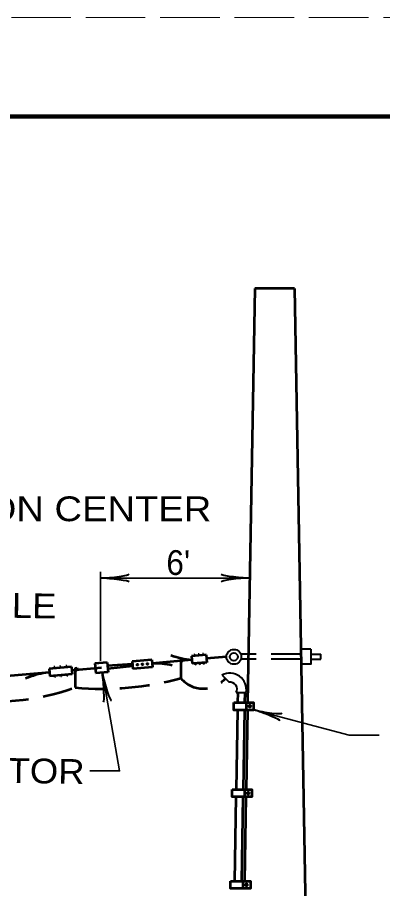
# Model space of a CAD drawing. Extents: x 12366 to 13046, y 9129 to 9570.
# Drawn here: x 12629.1 to 12665.9, y 9481.6 to 9569.5 of the extents above; entities that cross this region are included whole.
import ezdxf
from ezdxf.enums import TextEntityAlignment as Align

# ---------------------------------------------------------------- set-up
doc = ezdxf.new("R2010")
doc.units = 0
doc.linetypes.add('LONG_DASHED', pattern=[7.5, 6, -1.5])
doc.linetypes.add('MEDIUM_DASHED', pattern=[4.5, 3, -1.5])
doc.layers.add('1', color=7, linetype='Continuous', lineweight=53)
doc.layers.add('61', color=7, linetype='Continuous', lineweight=35)

msp = doc.modelspace()

# ---------------------------------------------------------------- linework, layer by layer
at = {"layer": '1'}
for p, q in [((12653.031, 9542.164), (12652.302, 9500.379)), ((12657.031, 9542.164), (12653.031, 9542.164)), ((12657.031, 9542.164), (12659.562, 9397.186)), ((12648.144, 9505.178), (12646.649, 9505.047)), ((12647.019, 9505.18), (12646.919, 9505.171)), ((12646.919, 9505.171), (12646.928, 9505.071)), ((12646.927, 9505.172), (12646.936, 9505.072)), ((12646.93, 9505.172), (12646.939, 9505.072)), ((12646.935, 9505.172), (12646.944, 9505.073)), ((12646.943, 9505.173), (12646.952, 9505.073)), ((12646.949, 9505.173), (12646.957, 9505.074)), ((12646.95, 9505.174), (12646.959, 9505.074)), ((12646.956, 9505.174), (12646.965, 9505.075)), ((12646.962, 9505.175), (12646.97, 9505.075)), ((12646.966, 9505.175), (12646.974, 9505.075)), ((12646.975, 9505.176), (12646.984, 9505.076)), ((12646.982, 9505.176), (12646.991, 9505.077)), ((12646.992, 9505.177), (12647, 9505.078)), ((12646.993, 9505.177), (12647.002, 9505.078)), ((12646.995, 9505.178), (12647.004, 9505.078)), ((12646.997, 9505.178), (12647.006, 9505.078)), ((12647.001, 9505.178), (12647.01, 9505.078)), ((12647.008, 9505.179), (12647.017, 9505.079)), ((12647.012, 9505.179), (12647.021, 9505.079)), ((12647.019, 9505.18), (12647.028, 9505.08)), ((12647.438, 9505.216), (12647.338, 9505.208)), ((12647.338, 9505.208), (12647.346, 9505.108)), ((12647.341, 9505.208), (12647.349, 9505.108)), ((12647.35, 9505.209), (12647.358, 9505.109)), ((12647.357, 9505.209), (12647.366, 9505.11)), ((12647.365, 9505.21), (12647.373, 9505.11)), ((12647.374, 9505.211), (12647.383, 9505.111)), ((12647.376, 9505.211), (12647.385, 9505.111)), ((12647.384, 9505.212), (12647.392, 9505.112)), ((12647.388, 9505.212), (12647.396, 9505.112)), ((12647.391, 9505.212), (12647.4, 9505.113)), ((12647.397, 9505.213), (12647.406, 9505.113)), ((12647.401, 9505.213), (12647.41, 9505.113)), ((12647.407, 9505.214), (12647.415, 9505.114)), ((12647.414, 9505.214), (12647.423, 9505.115)), ((12647.418, 9505.215), (12647.427, 9505.115)), ((12647.42, 9505.215), (12647.429, 9505.115)), ((12647.422, 9505.215), (12647.43, 9505.115)), ((12647.43, 9505.216), (12647.439, 9505.116)), ((12647.438, 9505.216), (12647.446, 9505.117)), ((12647.856, 9505.253), (12647.756, 9505.244)), ((12647.756, 9505.244), (12647.765, 9505.145)), ((12647.761, 9505.245), (12647.77, 9505.145)), ((12647.77, 9505.245), (12647.779, 9505.146)), ((12647.777, 9505.246), (12647.786, 9505.146)), ((12647.787, 9505.247), (12647.796, 9505.147)), ((12647.787, 9505.247), (12647.796, 9505.147)), ((12647.792, 9505.247), (12647.801, 9505.148)), ((12647.798, 9505.248), (12647.807, 9505.148)), ((12647.8, 9505.248), (12647.809, 9505.148)), ((12647.806, 9505.248), (12647.815, 9505.149)), ((12647.813, 9505.249), (12647.822, 9505.15)), ((12647.819, 9505.25), (12647.828, 9505.15)), ((12647.829, 9505.251), (12647.838, 9505.151)), ((12647.833, 9505.251), (12647.842, 9505.151)), ((12647.839, 9505.251), (12647.847, 9505.152)), ((12647.842, 9505.252), (12647.851, 9505.152)), ((12647.848, 9505.252), (12647.857, 9505.153)), ((12647.856, 9505.253), (12647.865, 9505.153)), ((12648.144, 9505.178), (12648.209, 9504.431)), ((12638.16, 9504.428), (12636.915, 9504.319)), ((12636.915, 9504.319), (12637.002, 9503.323)), ((12638.16, 9504.428), (12638.248, 9503.432)), ((12642.664, 9504.699), (12640.672, 9504.524)), ((12640.672, 9504.524), (12640.737, 9503.777)), ((12642.664, 9504.699), (12642.73, 9503.951)), ((12646.682, 9504.673), (12642.697, 9504.325)), ((12645.562, 9504.779), (12645.761, 9504.796)), ((12645.562, 9504.779), (12645.579, 9504.579)), ((12645.566, 9504.729), (12645.716, 9504.742)), ((12645.566, 9504.729), (12645.579, 9504.579)), ((12645.575, 9504.78), (12645.593, 9504.581)), ((12645.579, 9504.579), (12645.779, 9504.597)), ((12645.579, 9504.579), (12645.729, 9504.592)), ((12645.579, 9504.579), (12645.579, 9502.829)), ((12645.58, 9504.73), (12645.593, 9504.581)), ((12645.591, 9504.781), (12645.608, 9504.582)), ((12645.595, 9504.731), (12645.608, 9504.582)), ((12645.606, 9504.783), (12645.623, 9504.583)), ((12645.61, 9504.733), (12645.623, 9504.583)), ((12645.621, 9504.784), (12645.638, 9504.585)), ((12645.625, 9504.734), (12645.638, 9504.585)), ((12645.629, 9504.785), (12645.646, 9504.585)), ((12645.639, 9504.785), (12645.657, 9504.586)), ((12645.644, 9504.736), (12645.657, 9504.586)), ((12645.651, 9504.786), (12645.668, 9504.587)), ((12645.655, 9504.737), (12645.668, 9504.587)), ((12645.661, 9504.787), (12645.679, 9504.588)), ((12645.67, 9504.788), (12645.687, 9504.589)), ((12645.674, 9504.738), (12645.687, 9504.589)), ((12645.685, 9504.789), (12645.702, 9504.59)), ((12645.689, 9504.74), (12645.702, 9504.59)), ((12645.7, 9504.791), (12645.717, 9504.592)), ((12645.704, 9504.741), (12645.717, 9504.592)), ((12645.711, 9504.792), (12645.729, 9504.592)), ((12645.716, 9504.742), (12645.729, 9504.592)), ((12645.722, 9504.793), (12645.74, 9504.593)), ((12645.732, 9504.793), (12645.749, 9504.594)), ((12645.742, 9504.794), (12645.759, 9504.595)), ((12645.752, 9504.795), (12645.769, 9504.596)), ((12645.761, 9504.796), (12645.779, 9504.597)), ((12646.649, 9505.047), (12646.715, 9504.3)), ((12648.209, 9504.431), (12646.715, 9504.3)), ((12646.994, 9504.324), (12647.002, 9504.224)), ((12647.003, 9504.325), (12647.012, 9504.224)), ((12647.007, 9504.325), (12647.015, 9504.225)), ((12647.012, 9504.326), (12647.021, 9504.225)), ((12647.018, 9504.326), (12647.027, 9504.226)), ((12647.025, 9504.327), (12647.034, 9504.226)), ((12647.034, 9504.328), (12647.043, 9504.227)), ((12647.042, 9504.328), (12647.051, 9504.228)), ((12647.047, 9504.329), (12647.056, 9504.228)), ((12647.055, 9504.33), (12647.064, 9504.229)), ((12647.062, 9504.33), (12647.071, 9504.23)), ((12647.072, 9504.331), (12647.081, 9504.23)), ((12647.074, 9504.331), (12647.082, 9504.231)), ((12647.075, 9504.331), (12647.084, 9504.231)), ((12647.083, 9504.332), (12647.092, 9504.231)), ((12647.093, 9504.333), (12647.102, 9504.232)), ((12647.412, 9504.361), (12647.421, 9504.26)), ((12647.416, 9504.361), (12647.425, 9504.261)), ((12647.424, 9504.362), (12647.432, 9504.261)), ((12647.429, 9504.362), (12647.438, 9504.262)), ((12647.439, 9504.363), (12647.447, 9504.262)), ((12647.441, 9504.363), (12647.449, 9504.263)), ((12647.453, 9504.364), (12647.462, 9504.264)), ((12647.462, 9504.365), (12647.471, 9504.265)), ((12647.476, 9504.366), (12647.485, 9504.266)), ((12647.483, 9504.367), (12647.492, 9504.266)), ((12647.489, 9504.368), (12647.498, 9504.267)), ((12647.496, 9504.368), (12647.505, 9504.268)), ((12647.506, 9504.369), (12647.515, 9504.268)), ((12647.512, 9504.37), (12647.52, 9504.269)), ((12647.83, 9504.397), (12647.839, 9504.297)), ((12647.839, 9504.398), (12647.848, 9504.298)), ((12647.939, 9504.306), (12647.839, 9504.297)), ((12647.844, 9504.399), (12647.853, 9504.298)), ((12647.848, 9504.399), (12647.857, 9504.298)), ((12647.851, 9504.399), (12647.86, 9504.299)), ((12647.852, 9504.399), (12647.86, 9504.299)), ((12647.859, 9504.4), (12647.868, 9504.299)), ((12647.865, 9504.4), (12647.874, 9504.3)), ((12647.87, 9504.401), (12647.879, 9504.3)), ((12647.878, 9504.402), (12647.886, 9504.301)), ((12647.882, 9504.402), (12647.891, 9504.301)), ((12647.887, 9504.403), (12647.896, 9504.302)), ((12647.893, 9504.403), (12647.902, 9504.302)), ((12647.901, 9504.404), (12647.909, 9504.303)), ((12647.906, 9504.404), (12647.915, 9504.303)), ((12647.914, 9504.405), (12647.923, 9504.304)), ((12647.914, 9504.405), (12647.923, 9504.304)), ((12647.918, 9504.405), (12647.927, 9504.305)), ((12647.924, 9504.406), (12647.932, 9504.305)), ((12647.93, 9504.406), (12647.939, 9504.306)), ((12650.169, 9504.978), (12648.176, 9504.804)), ((12632.351, 9503.418), (12561.823, 9497.248)), ((12634.56, 9503.988), (12632.319, 9503.792)), ((12632.319, 9503.792), (12632.384, 9503.045)), ((12632.87, 9503.943), (12632.77, 9503.934)), ((12632.779, 9503.832), (12632.77, 9503.934)), ((12632.78, 9503.832), (12632.771, 9503.934)), ((12632.782, 9503.832), (12632.773, 9503.935)), ((12632.791, 9503.833), (12632.782, 9503.935)), ((12632.793, 9503.833), (12632.784, 9503.936)), ((12632.793, 9503.833), (12632.784, 9503.936)), ((12632.802, 9503.834), (12632.793, 9503.936)), ((12632.804, 9503.834), (12632.795, 9503.936)), ((12632.804, 9503.834), (12632.795, 9503.936)), ((12632.809, 9503.835), (12632.8, 9503.937)), ((12632.81, 9503.835), (12632.801, 9503.937)), ((12632.817, 9503.835), (12632.808, 9503.938)), ((12632.826, 9503.836), (12632.817, 9503.939)), ((12632.828, 9503.836), (12632.819, 9503.939)), ((12632.834, 9503.837), (12632.825, 9503.939)), ((12632.841, 9503.838), (12632.832, 9503.94)), ((12632.848, 9503.838), (12632.839, 9503.94)), ((12632.848, 9503.838), (12632.839, 9503.94)), ((12632.854, 9503.839), (12632.845, 9503.941)), ((12632.86, 9503.839), (12632.851, 9503.941)), ((12632.863, 9503.84), (12632.854, 9503.942)), ((12632.863, 9503.84), (12632.855, 9503.942)), ((12632.871, 9503.84), (12632.862, 9503.942)), ((12632.875, 9503.841), (12632.866, 9503.943)), ((12632.879, 9503.841), (12632.87, 9503.943)), ((12633.48, 9503.996), (12633.381, 9503.987)), ((12633.39, 9503.886), (12633.381, 9503.987)), ((12633.396, 9503.886), (12633.387, 9503.988)), ((12633.4, 9503.887), (12633.391, 9503.988)), ((12633.404, 9503.887), (12633.395, 9503.989)), ((12633.411, 9503.887), (12633.402, 9503.989)), ((12633.414, 9503.888), (12633.405, 9503.99)), ((12633.416, 9503.888), (12633.407, 9503.99)), ((12633.424, 9503.889), (12633.415, 9503.99)), ((12633.431, 9503.889), (12633.422, 9503.991)), ((12633.431, 9503.889), (12633.423, 9503.991)), ((12633.431, 9503.889), (12633.423, 9503.991)), ((12633.435, 9503.89), (12633.426, 9503.991)), ((12633.44, 9503.89), (12633.431, 9503.992)), ((12633.441, 9503.89), (12633.432, 9503.992)), ((12633.444, 9503.89), (12633.435, 9503.992)), ((12633.452, 9503.891), (12633.443, 9503.993)), ((12633.452, 9503.891), (12633.443, 9503.993)), ((12633.456, 9503.891), (12633.447, 9503.993)), ((12633.457, 9503.891), (12633.448, 9503.993)), ((12633.459, 9503.892), (12633.45, 9503.994)), ((12633.459, 9503.892), (12633.45, 9503.994)), ((12633.463, 9503.892), (12633.454, 9503.994)), ((12633.465, 9503.892), (12633.456, 9503.994)), ((12633.47, 9503.893), (12633.461, 9503.994)), ((12633.474, 9503.893), (12633.465, 9503.995)), ((12633.478, 9503.893), (12633.469, 9503.995)), ((12633.48, 9503.894), (12633.471, 9503.995)), ((12633.483, 9503.894), (12633.474, 9503.996)), ((12633.489, 9503.894), (12633.48, 9503.996)), ((12634.091, 9504.041), (12633.992, 9504.032)), ((12634, 9503.939), (12633.992, 9504.032)), ((12634.008, 9503.94), (12634, 9504.033)), ((12634.01, 9503.94), (12634.002, 9504.033)), ((12634.012, 9503.94), (12634.004, 9504.033)), ((12634.019, 9503.941), (12634.011, 9504.034)), ((12634.021, 9503.941), (12634.013, 9504.034)), ((12634.023, 9503.941), (12634.015, 9504.034)), ((12634.029, 9503.942), (12634.021, 9504.035)), ((12634.036, 9503.942), (12634.028, 9504.035)), ((12634.038, 9503.942), (12634.03, 9504.036)), ((12634.045, 9503.943), (12634.037, 9504.036)), ((12634.051, 9503.943), (12634.043, 9504.037)), ((12634.057, 9503.944), (12634.048, 9504.037)), ((12634.06, 9503.944), (12634.052, 9504.038)), ((12634.066, 9503.945), (12634.058, 9504.038)), ((12634.074, 9503.945), (12634.066, 9504.039)), ((12634.078, 9503.946), (12634.07, 9504.039)), ((12634.083, 9503.946), (12634.075, 9504.04)), ((12634.091, 9503.947), (12634.082, 9504.04)), ((12634.096, 9503.947), (12634.088, 9504.041)), ((12634.099, 9503.948), (12634.091, 9504.041)), ((12634.56, 9503.988), (12634.626, 9503.241)), ((12637.581, 9503.876), (12634.593, 9503.614)), ((12634.92, 9503.846), (12635.119, 9503.863)), ((12634.92, 9503.846), (12634.938, 9503.646)), ((12634.924, 9503.796), (12635.074, 9503.809)), ((12634.924, 9503.796), (12634.938, 9503.646)), ((12634.934, 9503.847), (12634.951, 9503.648)), ((12634.938, 9503.797), (12634.951, 9503.648)), ((12634.938, 9503.646), (12635.137, 9503.664)), ((12634.938, 9503.646), (12635.087, 9503.659)), ((12634.938, 9503.646), (12634.938, 9501.896)), ((12634.949, 9503.848), (12634.966, 9503.649)), ((12634.953, 9503.798), (12634.966, 9503.649)), ((12634.964, 9503.849), (12634.981, 9503.65)), ((12634.968, 9503.799), (12634.981, 9503.65)), ((12634.979, 9503.851), (12634.996, 9503.651)), ((12634.983, 9503.801), (12634.996, 9503.651)), ((12634.987, 9503.851), (12635.004, 9503.652)), ((12634.997, 9503.852), (12635.015, 9503.653)), ((12635.002, 9503.802), (12635.015, 9503.653)), ((12635.009, 9503.853), (12635.026, 9503.654)), ((12635.013, 9503.803), (12635.026, 9503.654)), ((12635.02, 9503.854), (12635.037, 9503.655)), ((12635.028, 9503.855), (12635.045, 9503.656)), ((12635.032, 9503.805), (12635.045, 9503.656)), ((12635.043, 9503.856), (12635.06, 9503.657)), ((12635.047, 9503.806), (12635.06, 9503.657)), ((12635.058, 9503.858), (12635.075, 9503.658)), ((12635.062, 9503.808), (12635.075, 9503.658)), ((12635.07, 9503.859), (12635.087, 9503.659)), ((12635.074, 9503.809), (12635.087, 9503.659)), ((12635.08, 9503.86), (12635.098, 9503.66)), ((12635.09, 9503.86), (12635.107, 9503.661)), ((12635.1, 9503.861), (12635.118, 9503.662)), ((12635.11, 9503.862), (12635.127, 9503.663)), ((12635.119, 9503.863), (12635.137, 9503.664)), ((12638.248, 9503.432), (12637.002, 9503.323)), ((12640.696, 9504.247), (12638.192, 9504.072)), ((12640.713, 9504.051), (12638.216, 9503.789)), ((12642.73, 9503.951), (12640.737, 9503.777)), ((12647.102, 9504.232), (12647.002, 9504.224)), ((12647.52, 9504.269), (12647.421, 9504.26)), ((12633.505, 9503.143), (12632.384, 9503.045)), ((12632.854, 9502.985), (12632.845, 9503.085)), ((12632.86, 9502.986), (12632.851, 9503.086)), ((12632.953, 9502.994), (12632.854, 9502.985)), ((12632.869, 9502.987), (12632.86, 9503.086)), ((12632.875, 9502.987), (12632.866, 9503.087)), ((12632.878, 9502.988), (12632.87, 9503.087)), ((12632.88, 9502.988), (12632.872, 9503.087)), ((12632.882, 9502.988), (12632.874, 9503.087)), ((12632.888, 9502.988), (12632.879, 9503.088)), ((12632.888, 9502.988), (12632.879, 9503.088)), ((12632.897, 9502.989), (12632.888, 9503.089)), ((12632.903, 9502.99), (12632.894, 9503.089)), ((12632.905, 9502.99), (12632.896, 9503.09)), ((12632.908, 9502.99), (12632.9, 9503.09)), ((12632.908, 9502.99), (12632.9, 9503.09)), ((12632.918, 9502.991), (12632.909, 9503.091)), ((12632.925, 9502.992), (12632.916, 9503.091)), ((12632.931, 9502.992), (12632.922, 9503.092)), ((12632.933, 9502.992), (12632.924, 9503.092)), ((12632.934, 9502.993), (12632.926, 9503.092)), ((12632.936, 9502.993), (12632.928, 9503.092)), ((12632.94, 9502.993), (12632.931, 9503.093)), ((12632.944, 9502.993), (12632.935, 9503.093)), ((12632.945, 9502.994), (12632.937, 9503.093)), ((12632.953, 9502.994), (12632.944, 9503.094)), ((12633.464, 9503.039), (12633.455, 9503.138)), ((12633.467, 9503.039), (12633.459, 9503.139)), ((12633.563, 9503.048), (12633.464, 9503.039)), ((12633.475, 9503.04), (12633.466, 9503.139)), ((12633.475, 9503.04), (12633.466, 9503.139)), ((12633.477, 9503.04), (12633.468, 9503.14)), ((12633.486, 9503.041), (12633.477, 9503.14)), ((12633.49, 9503.041), (12633.481, 9503.141)), ((12633.497, 9503.042), (12633.489, 9503.141)), ((12633.499, 9503.042), (12633.491, 9503.141)), ((12633.507, 9503.043), (12633.498, 9503.142)), ((12633.51, 9503.043), (12633.502, 9503.142)), ((12634.626, 9503.241), (12633.505, 9503.143)), ((12633.513, 9503.043), (12633.505, 9503.143)), ((12633.518, 9503.044), (12633.509, 9503.143)), ((12633.518, 9503.044), (12633.509, 9503.143)), ((12633.525, 9503.044), (12633.517, 9503.144)), ((12633.533, 9503.045), (12633.524, 9503.144)), ((12633.536, 9503.045), (12633.528, 9503.145)), ((12633.542, 9503.046), (12633.534, 9503.145)), ((12633.547, 9503.046), (12633.539, 9503.146)), ((12633.547, 9503.046), (12633.539, 9503.146)), ((12633.557, 9503.047), (12633.548, 9503.146)), ((12633.563, 9503.048), (12633.555, 9503.147)), ((12634.074, 9503.092), (12634.065, 9503.192)), ((12634.078, 9503.093), (12634.07, 9503.192)), ((12634.082, 9503.093), (12634.073, 9503.193)), ((12634.173, 9503.101), (12634.074, 9503.092)), ((12634.091, 9503.094), (12634.083, 9503.193)), ((12634.101, 9503.095), (12634.092, 9503.194)), ((12634.107, 9503.095), (12634.098, 9503.195)), ((12634.114, 9503.096), (12634.105, 9503.195)), ((12634.121, 9503.096), (12634.112, 9503.196)), ((12634.125, 9503.097), (12634.117, 9503.196)), ((12634.128, 9503.097), (12634.119, 9503.197)), ((12634.136, 9503.098), (12634.128, 9503.197)), ((12634.136, 9503.098), (12634.128, 9503.197)), ((12634.144, 9503.098), (12634.135, 9503.198)), ((12634.145, 9503.099), (12634.137, 9503.198)), ((12634.155, 9503.099), (12634.146, 9503.199)), ((12634.155, 9503.099), (12634.146, 9503.199)), ((12634.162, 9503.1), (12634.154, 9503.199)), ((12634.17, 9503.101), (12634.162, 9503.2)), ((12634.173, 9503.101), (12634.165, 9503.2)), ((12651.318, 9501.38), (12651.3, 9500.379)), ((12652.018, 9501.38), (12652, 9500.364)), ((12652.152, 9500.371), (12652.152, 9499.621)), ((12651.287, 9499.621), (12651.147, 9491.608)), ((12651.987, 9499.613), (12651.847, 9491.608)), ((12652.289, 9499.605), (12652.149, 9491.608)), ((12651.994, 9491.6), (12651.994, 9490.85)), ((12651.134, 9490.857), (12650.986, 9482.352)), ((12651.834, 9490.842), (12651.686, 9482.352)), ((12652.136, 9490.849), (12651.987, 9482.348)), ((12651.832, 9482.348), (12651.832, 9481.598))]:
    msp.add_line(p, q, dxfattribs=at)
at = {"layer": '1', "lineweight": 35}
for p, q in [((12637.479, 9504.581), (12637.479, 9513.581)), ((12637.479, 9512.941), (12652.521, 9512.941))]:
    msp.add_line(p, q, dxfattribs=at)
at = {"layer": '1', "linetype": 'MEDIUM_DASHED', "lineweight": 40}
for p, q in [((12657.678, 9505.254), (12651.636, 9505.254)), ((12657.678, 9504.754), (12651.636, 9504.754))]:
    msp.add_line(p, q, dxfattribs=at)
at = {"layer": '1', "lineweight": 40}
for p, q in [((12658.694, 9505.754), (12657.688, 9505.754)), ((12658.694, 9505.254), (12659.678, 9505.254)), ((12659.678, 9504.754), (12659.678, 9505.254)), ((12658.694, 9504.754), (12659.678, 9504.754)), ((12649.724, 9503.132), (12650.431, 9502.425)), ((12651.152, 9501.38), (12652.152, 9501.38))]:
    msp.add_line(p, q, dxfattribs=at)
at = {"layer": '1', "lineweight": 25}
for p, q in [((12642.697, 9504.325), (12642.898, 9504.342)), ((12648.176, 9504.804), (12648.421, 9504.826)), ((12632.351, 9503.418), (12631.971, 9503.385)), ((12634.593, 9503.614), (12634.984, 9503.649))]:
    msp.add_line(p, q, dxfattribs=at)
at = {"layer": '1', "lineweight": 40}
msp.add_lwpolyline([(12658.694, 9505.754), (12658.694, 9504.254), (12657.691, 9504.254)], dxfattribs=at)
at = {"layer": '1', "lineweight": 35}
for points in [[(12637.672, 9503.327), (12639.409, 9493.479), (12636.409, 9493.479)], [(12652.894, 9499.655), (12662.553, 9497.067), (12665.553, 9497.067)]]:
    msp.add_lwpolyline(points, dxfattribs=at)
at = {"layer": '1'}
for points in [[(12650.902, 9500.371), (12652.902, 9500.371), (12652.902, 9499.621), (12650.902, 9499.621)], [(12650.744, 9491.6), (12652.744, 9491.6), (12652.744, 9490.85), (12650.744, 9490.85)], [(12650.582, 9482.348), (12652.582, 9482.348), (12652.582, 9481.598), (12650.582, 9481.598)]]:
    msp.add_lwpolyline(points, close=True, dxfattribs=at)
at = {"layer": '1', "lineweight": 40}
for centre, radius in [((12650.92, 9504.989), 0.75), ((12650.923, 9504.987), 0.394)]:
    msp.add_circle(centre, radius, dxfattribs=at)
at = {"layer": '1'}
for centre, radius in [((12641.703, 9504.24), 0.05), ((12642.201, 9504.281), 0.05), ((12641.205, 9504.195), 0.05), ((12652.516, 9500), 0.1), ((12652.358, 9491.228), 0.1), ((12652.196, 9481.977), 0.1)]:
    msp.add_circle(centre, radius, dxfattribs=at)
for centre, start, end in [((12642.878, 9495.635), 77.79454, 91.19453), ((12647.561, 9513.321), 249.94661, 264.19453), ((12633.301, 9494.796), 98.80547, 112.81313)]:
    msp.add_arc(centre, 8.692, start, end, dxfattribs=at)
at = {"layer": '1', "linetype": 'MEDIUM_DASHED'}
for centre, radius, start, end in [((12637.716, 9531.352), 29.587, 264.61066, 285.41207), ((12647.834, 9504.723), 2.944, 220.02355, 318.67214), ((12626.841, 9524.298), 23.82, 260.14661, 289.87015)]:
    msp.add_arc(centre, radius, start, end, dxfattribs=at)
at = {"layer": '1', "lineweight": 40}
for centre, radius, start, end in [((12650.523, 9501.682), 1.656, 349.50124, 118.8707), ((12650.533, 9501.725), 0.708, 330.86779, 98.35179)]:
    msp.add_arc(centre, radius, start, end, dxfattribs=at)
for centre, major_axis, ratio, start_param, end_param in [((12638.57, 9513.218), (-1.786, -0.156), 0.122415, 0.896353, 3.141593), ((12651.401, 9513.153), (1.756, -0.176), 0.07063, 3.140715, 5.41811), ((12638.6, 9512.73), (1.756, -0.176), 0.07063, 6.282307, 8.559703), ((12651.43, 9512.665), (1.786, 0.156), 0.122415, 0.896353, 3.141593), ((12637.658, 9502.187), (-0.132, 1.76), 0.07063, 3.140715, 5.41811), ((12638.134, 9502.3), (-0.464, 1.731), 0.122415, 0.896353, 3.141593), ((12653.922, 9499.161), (1.651, -0.624), 0.07063, 6.282307, 8.559703), ((12654.02, 9499.64), (-1.765, 0.311), 0.122415, 0.896353, 3.141593)]:
    msp.add_ellipse(centre, major_axis=major_axis, ratio=ratio, start_param=start_param, end_param=end_param, dxfattribs=at)
at = {"layer": '61', "linetype": 'LONG_DASHED', "lineweight": 13}
msp.add_line((12365.992, 9569.533), (13046.012, 9569.533), dxfattribs=at)
at = {"layer": '61', "lineweight": 158}
msp.add_lwpolyline([(13035.032, 9559.533), (12395.992, 9559.533), (12395.992, 9139.513)], dxfattribs=at)

# ---------------------------------------------------------------- texts
at = {"layer": '1', "width": 1.15}
msp.add_text('CABLE RINGS 15" ON CENTER', height=2.5, dxfattribs=at).set_placement((12592.377, 9518.681))
at = {"layer": '1', "width": 0.95}
msp.add_text("6'", height=2.5, rotation=359, dxfattribs=at).set_placement((12645.283, 9513.25), align=Align.CENTER)
at = {"layer": '1', "width": 1.1}
msp.add_text('MESSENGER CABLE', height=2.5, rotation=359, dxfattribs=at).set_placement((12596.444, 9509.494))
msp.add_text('STRAIN INSULATOR', height=2.5, rotation=359, dxfattribs=at).set_placement((12635.852, 9492.139), align=Align.RIGHT)

doc.saveas('drawing.dxf')
